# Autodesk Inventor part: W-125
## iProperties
Author: Administrator
Revision Number: A
Created: 2001-03
Part Number: W-125
Document SubType Name: Modeling
Designer: Administrator
Control State: 0
Master: False
Checked Out: False
PropertySet Name: Design Tracking Control
Shininess: 20.0
PropertySet Name: _Private Model Information
Density: 0.0
Volumn: 0.0
Area: 0.0
PropertySet Name: Model Information
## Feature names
1. Revolution1
2. Fillet1
